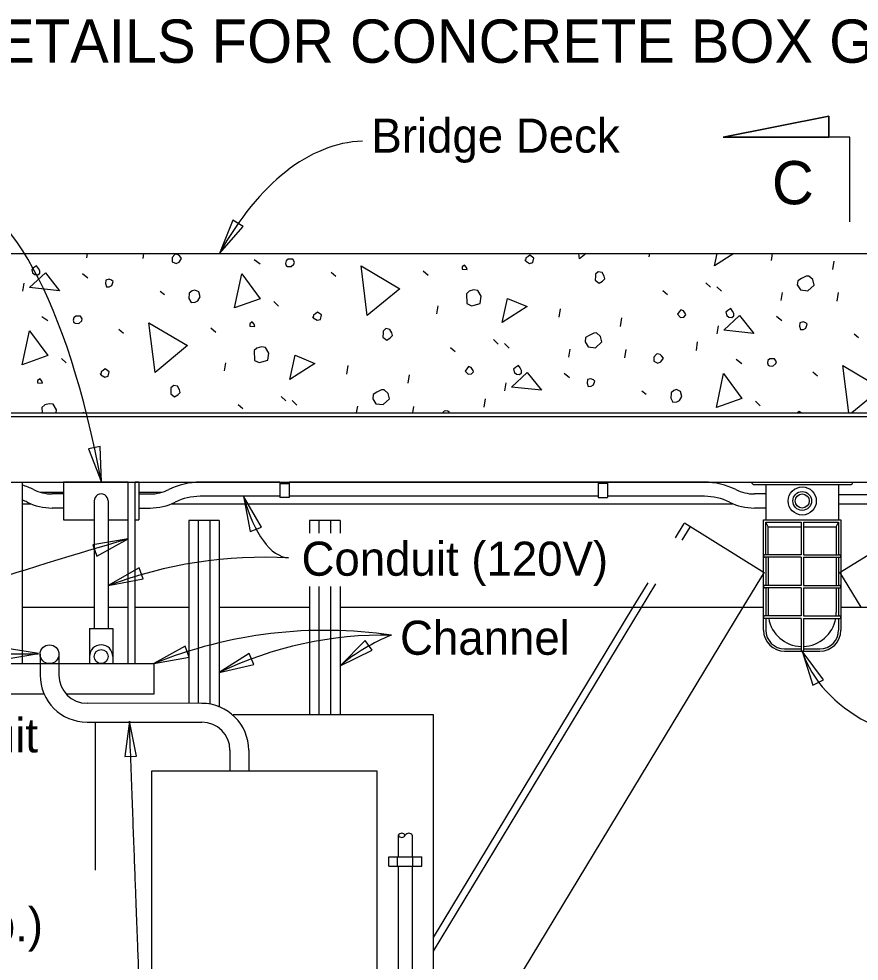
# Model space of a CAD drawing. Extents: x 0 to 30.8, y 0 to 21.2.
# Drawn here: x 4.493 to 8.221, y 5.394 to 9.576 of the extents above; entities that cross this region are included whole.
import ezdxf

# ---------------------------------------------------------------- set-up
doc = ezdxf.new("R2010")
doc.units = 0
for name, color, linetype in [('Dimension', 7, 'Continuous'), ('Lighting', 7, 'Continuous'), ('Miscellaneous', 7, 'Continuous'), ('SteelGirder', 7, 'Continuous'), ('SteelGirder_h', 7, 'Continuous'), ('SupstrConc', 7, 'Continuous'), ('TextStructures', 7, 'Continuous')]:
    doc.layers.add(name, color=color, linetype=linetype)

msp = doc.modelspace()

# ---------------------------------------------------------------- linework, layer by layer
at = {"layer": 'Dimension'}
for p, q in [((7.6172, 9.0507), (8.0859, 9.1444)), ((8.0859, 9.1444), (8.0859, 9.0507)), ((8.1797, 9.0507), (7.6172, 9.0507)), ((8.1797, 8.6757), (8.1797, 9.0507))]:
    msp.add_line(p, q, dxfattribs=at)
for points in [[(8.0859, 9.0507), (8.0859, 9.1444), (7.6172, 9.0507)], [(5.3832, 8.5353), (5.4879, 8.6542), (5.4428, 8.682)], [(4.8595, 7.5197), (4.8546, 7.678), (4.8027, 7.6676)], [(5.4894, 7.4572), (5.5198, 7.3017), (5.5693, 7.3204)], [(4.9783, 7.2679), (4.822, 7.2423), (4.8391, 7.1922)], [(4.8897, 7.0606), (5.0452, 7.0907), (5.0266, 7.1402)], [(5.918, 6.705), (6.0607, 6.7738), (6.03, 6.8169)], [(4.5805, 6.7589), (4.4243, 6.7853), (4.4243, 6.7324)], [(5.0928, 6.7147), (5.2487, 6.7428), (5.2307, 6.7925)], [(5.3822, 6.6746), (5.5364, 6.7111), (5.5157, 6.7599)], [(7.9682, 6.7697), (8.0155, 6.6185), (8.0627, 6.6425)], [(4.9837, 6.4589), (4.963, 6.3018), (5.0159, 6.3037)]]:
    msp.add_lwpolyline(points, close=True, dxfattribs=at)
for centre, radius, start, end in [((5.5854, 5.207), 1.9799, 86.9707, 110.5746), ((5.8523, 4.8354), 2.0269, 81.6635, 112.0069), ((6.1133, 5.1541), 1.6871, 88.8828, 115.6789), ((6.4507, 6.0706), 0.8283, 111.5678, 130.0212)]:
    msp.add_arc(centre, radius, start, end, dxfattribs=at)
for centre, major_axis, ratio, start_param, end_param in [((6.1283, 6.6665), (0.1111, -2.3674), 0.464296, 3.141604, 3.781059), ((4.1852, 6.2941), (0.0332, -2.5173), 0.313255, 2.075166, 3.141607), ((5.7691, 8.2544), (0.079, 1.0703), 0.315754, 2.434073, 3.141613), ((9.2695, 7.2066), (1.3013, 0.4369), 0.58496, 3.141593, 4.152777)]:
    msp.add_ellipse(centre, major_axis=major_axis, ratio=ratio, start_param=start_param, end_param=end_param, dxfattribs=at)
for points, degree in [([(4.9783, 7.2679), (4.6826, 7.1814), (4.1926, 7.0333), (3.6822, 6.8035), (3.5444, 6.6555), (3.3556, 6.3798), (3.4596, 6.0576), (3.4353, 5.8356), (3.5477, 5.8254)], 3), ([(3.8226, 6.4065), (3.7639, 6.427), (3.7332, 6.478), (3.8583, 6.6108), (4.1824, 6.7333), (4.3074, 6.7588), (4.5805, 6.7588)], 2), ([(2.6234, 4.9322), (4.0961, 4.9424), (5.0399, 4.9935), (5.0194, 5.4888), (4.9837, 6.4589)], 2)]:
    msp.add_open_spline(points, degree=degree, dxfattribs=at)
at = {"layer": 'Lighting'}
for p, q in [((4.6917, 7.5197), (4.6917, 7.353)), ((4.9783, 7.5197), (4.6917, 7.5197)), ((5.025, 7.5197), (5.0095, 7.5197)), ((5.025, 7.5197), (5.025, 7.353)), ((5.6513, 7.5197), (5.297, 7.5197)), ((7.0625, 7.5197), (5.693, 7.5197)), ((7.5342, 7.5197), (7.1042, 7.5197)), ((7.7443, 7.5197), (8.1922, 7.5197)), ((7.7547, 7.5093), (8.1818, 7.5093)), ((7.8068, 7.5197), (8.1297, 7.5197)), ((7.8068, 7.5093), (7.8068, 7.353)), ((8.1297, 7.5093), (8.1297, 7.353)), ((4.6917, 7.4676), (4.6414, 7.4676)), ((5.025, 7.4676), (5.0754, 7.4676)), ((5.6513, 7.4572), (5.2969, 7.4572)), ((7.0625, 7.4572), (5.693, 7.4572)), ((7.5347, 7.4572), (7.1042, 7.4572)), ((7.8068, 7.4676), (7.7564, 7.4676)), ((4.6917, 7.4051), (4.6414, 7.4051)), ((4.8271, 7.4364), (4.8271, 6.8702)), ((4.8896, 7.4364), (4.8896, 6.8702)), ((5.025, 7.4051), (5.0754, 7.4051)), ((7.8068, 7.4051), (7.7564, 7.4051)), ((4.6917, 7.353), (4.8271, 7.353)), ((4.8896, 7.353), (4.9783, 7.353)), ((5.0095, 7.353), (5.025, 7.353)), ((5.2468, 7.3502), (5.2468, 6.5383)), ((5.3822, 7.3502), (5.2468, 7.3502)), ((5.2884, 7.3502), (5.2884, 6.5383)), ((5.3406, 7.3502), (5.3406, 6.5352)), ((5.3822, 7.3502), (5.3822, 6.5233)), ((5.918, 7.3502), (5.7826, 7.3502)), ((5.7826, 7.3502), (5.7826, 7.2938)), ((5.8242, 7.3502), (5.8242, 7.2938)), ((5.8764, 7.3502), (5.8764, 7.2938)), ((5.918, 7.3502), (5.918, 7.2938)), ((7.7964, 6.8634), (7.7964, 7.353)), ((7.7964, 7.353), (7.8068, 7.353)), ((7.8068, 7.353), (8.1297, 7.353)), ((7.8068, 7.1968), (7.8068, 7.3426)), ((7.8068, 7.3426), (7.963, 7.3426)), ((7.8172, 7.3218), (7.8068, 7.3426)), ((7.8172, 7.3218), (7.963, 7.3218)), ((7.963, 7.3426), (7.963, 7.1968)), ((7.9734, 7.3426), (8.1297, 7.3426)), ((7.9734, 7.3426), (7.9734, 7.1968)), ((7.9734, 7.3218), (8.1193, 7.3218)), ((8.1193, 7.3218), (8.1297, 7.3426)), ((8.1297, 7.353), (8.1401, 7.353)), ((8.1297, 7.3426), (8.1297, 7.1968)), ((8.1401, 7.353), (8.1401, 6.8634)), ((7.963, 7.1968), (7.8016, 7.1968)), ((7.9734, 7.1968), (8.1349, 7.1968)), ((7.963, 7.1864), (7.8016, 7.1864)), ((7.8068, 7.1864), (7.8068, 7.0614)), ((7.963, 7.1864), (7.963, 7.0614)), ((7.9734, 7.1864), (8.1349, 7.1864)), ((7.9734, 7.1864), (7.9734, 7.0614)), ((8.1297, 7.1864), (8.1297, 7.0614)), ((5.7826, 7.057), (5.7826, 6.4871)), ((5.8242, 7.057), (5.8242, 6.4871)), ((5.8764, 7.057), (5.8764, 6.4871)), ((5.918, 7.057), (5.918, 6.4871)), ((7.963, 7.0614), (7.8016, 7.0614)), ((7.963, 7.051), (7.8016, 7.051)), ((7.8068, 7.051), (7.8068, 6.926)), ((7.963, 7.051), (7.963, 6.926)), ((7.9734, 7.0614), (8.1349, 7.0614)), ((7.9734, 7.051), (8.1349, 7.051)), ((7.9734, 7.051), (7.9734, 6.926)), ((8.1297, 7.051), (8.1297, 6.926)), ((7.963, 6.926), (7.8016, 6.926)), ((7.963, 6.9156), (7.8016, 6.9156)), ((7.8068, 6.9156), (7.8068, 6.8634)), ((7.963, 6.9156), (7.963, 6.7749)), ((7.9734, 6.926), (8.1349, 6.926)), ((7.9734, 6.9156), (8.1349, 6.9156)), ((7.9734, 6.9156), (7.9734, 6.7749)), ((8.1297, 6.9156), (8.1297, 6.8634)), ((4.8063, 6.8702), (4.9104, 6.8702)), ((4.8063, 6.8702), (4.8063, 6.7147)), ((4.9104, 6.8702), (4.9104, 6.7147)), ((7.8901, 6.7801), (7.963, 6.7801)), ((7.9734, 6.7801), (8.0464, 6.7801)), ((4.5876, 6.7563), (4.5876, 6.6634)), ((4.6709, 6.7563), (4.6709, 6.6635)), ((7.8901, 6.7697), (8.0464, 6.7697)), ((4.3949, 6.7147), (5.0928, 6.7147)), ((5.0928, 6.7147), (5.0928, 6.5793)), ((4.6053, 6.5793), (4.3949, 6.5793)), ((5.0928, 6.5793), (4.7035, 6.5793)), ((5.3047, 6.5383), (4.7959, 6.5385)), ((4.7958, 6.4551), (5.3046, 6.4549)), ((5.4296, 6.3299), (5.4296, 6.2371)), ((5.513, 6.33), (5.513, 6.2371)), ((6.1761, 5.9527), (6.1761, 5.8576)), ((6.2387, 5.9527), (6.2387, 5.8576)), ((6.1761, 5.8159), (6.1761, 3.9083)), ((6.2387, 5.8159), (6.2387, 3.9083))]:
    msp.add_line(p, q, dxfattribs=at)
msp.add_lwpolyline([(6.0824, 6.2371), (5.0824, 6.2371), (5.0824, 3.4871), (6.0824, 3.4871)], close=True, dxfattribs=at)
for centre, radius in [((7.9682, 7.4364), 0.0625), ((7.9682, 7.4364), 0.0417), ((7.9682, 7.4364), 0.0312), ((4.6293, 6.7563), 0.0416), ((4.8584, 6.7459), 0.0312)]:
    msp.add_circle(centre, radius, dxfattribs=at)
for centre, radius, start, end in [((4.4191, 7.2072), 0.3125, 63.6116, 73.2157), ((4.6414, 7.6551), 0.1875, 243.6116, 270.0001), ((5.0754, 7.6551), 0.1875, 270.0001, 296.3886), ((5.2976, 7.2072), 0.3125, 90.0002, 116.3886), ((7.5342, 7.2072), 0.3125, 63.6115, 90.0001), ((7.7564, 7.6551), 0.1875, 243.6115, 270), ((7.7547, 7.5197), 0.0104, 180, 270), ((8.1818, 7.5197), 0.0104, 270, 0), ((4.8584, 7.4364), 0.0312, 359.9876, 180.0001), ((5.2976, 7.2072), 0.25, 90.0002, 116.3886), ((7.5342, 7.2072), 0.25, 63.6115, 89.8816), ((4.4191, 7.2072), 0.25, 63.6116, 68.8407), ((4.6414, 7.6551), 0.25, 243.6116, 270.0001), ((5.0754, 7.6551), 0.25, 270.0001, 296.3886), ((7.7564, 7.6551), 0.25, 243.6115, 270), ((7.8016, 7.1916), 0.0052, 89.9999, 270), ((8.1349, 7.1916), 0.0052, 270, 90.0001), ((7.8016, 7.0562), 0.0052, 89.9999, 270), ((8.1349, 7.0562), 0.0052, 270, 90.0001), ((7.8016, 6.9208), 0.0052, 89.9999, 270), ((8.1349, 6.9208), 0.0052, 270, 90.0001), ((7.8901, 6.8634), 0.0937, 180, 270), ((7.8901, 6.8634), 0.0833, 180, 270), ((8.0464, 6.8634), 0.0833, 270, 360), ((8.0464, 6.8634), 0.0937, 270, 360), ((4.8584, 6.7459), 0.052, 0.0163, 179.7051), ((7.9682, 6.7749), 0.0052, 179.9665, 0), ((4.7959, 6.6634), 0.2083, 180, 269.9792), ((4.7959, 6.6635), 0.125, 180, 269.9792), ((5.3047, 6.33), 0.2083, 0, 89.9792), ((5.3046, 6.3299), 0.125, 0, 89.9792), ((6.1918, 5.944), 0.0179, 29.0027, 150.9974), ((6.1918, 5.9614), 0.0179, 209.003, 330.9971), ((6.2231, 5.944), 0.0179, 29.0028, 150.9973)]:
    msp.add_arc(centre, radius, start, end, dxfattribs=at)
at = {"layer": 'Miscellaneous'}
for p, q in [((4.7952, 8.5161), (4.7985, 8.5353)), ((5.0445, 8.513), (5.0477, 8.5353)), ((7.2894, 8.5192), (7.2922, 8.5353)), ((7.8318, 8.5041), (7.8363, 8.5353)), ((5.5376, 8.508), (5.5634, 8.489)), ((8.1042, 8.4632), (8.1096, 8.5009)), ((5.8788, 8.4519), (5.8991, 8.434)), ((6.2862, 8.4575), (6.3096, 8.4379)), ((4.7752, 8.446), (4.7986, 8.4264)), ((4.5115, 8.3676), (4.5176, 8.4029)), ((5.1197, 8.3675), (5.1394, 8.3521)), ((7.3501, 8.3699), (7.3704, 8.352)), ((7.54, 8.4052), (7.5609, 8.3849)), ((7.5888, 8.3872), (7.6097, 8.367)), ((7.8742, 8.3265), (7.8803, 8.3618)), ((8.1235, 8.3235), (8.1289, 8.3611)), ((5.6239, 8.3214), (5.6448, 8.3012)), ((6.3476, 8.2669), (6.3537, 8.3022)), ((6.89, 8.2518), (6.8955, 8.2895)), ((4.5959, 8.2556), (4.6216, 8.2367)), ((7.1624, 8.2109), (7.1678, 8.2486)), ((7.8542, 8.2565), (7.8775, 8.2368)), ((4.937, 8.1995), (4.9573, 8.1817)), ((5.3444, 8.2051), (5.3678, 8.1855)), ((7.5905, 8.178), (7.5966, 8.2133)), ((8.1987, 8.178), (8.2184, 8.1625)), ((6.4084, 8.1175), (6.4287, 8.0997)), ((6.5982, 8.1529), (6.6191, 8.1326)), ((6.647, 8.1349), (6.668, 8.1146)), ((7.4989, 8.1043), (7.5044, 8.142)), ((6.9324, 8.0742), (6.9385, 8.1095)), ((7.1817, 8.0711), (7.1872, 8.1088)), ((4.6821, 8.0691), (4.703, 8.0488)), ((5.4058, 8.0145), (5.4119, 8.0498)), ((5.9482, 7.9994), (5.9537, 8.0371)), ((7.6748, 8.0661), (7.7006, 8.0471)), ((6.2206, 7.9585), (6.226, 7.9962)), ((6.9124, 8.0041), (6.9358, 7.9845)), ((8.016, 8.0099), (8.0363, 7.9921)), ((6.6487, 7.9257), (6.6548, 7.961)), ((7.2569, 7.9256), (7.2766, 7.9102)), ((5.4666, 7.8652), (5.4869, 7.8473)), ((5.6564, 7.9005), (5.6774, 7.8802)), ((5.7052, 7.8825), (5.7262, 7.8623)), ((6.5572, 7.852), (6.5626, 7.8897)), ((7.761, 7.8795), (7.782, 7.8593)), ((3.9317, 7.827), (8.7519, 7.827)), ((5.9915, 7.827), (5.9967, 7.8571)), ((6.2411, 7.827), (6.2454, 7.8564)), ((3.9359, 7.8114), (8.7519, 7.8114)), ((3.2598, 7.5197), (8.7519, 7.5197)), ((7.8172, 7.1968), (7.8172, 7.3218)), ((8.1193, 7.3218), (8.1193, 7.1968)), ((7.8172, 7.1864), (7.8172, 7.0614)), ((8.1193, 7.1864), (8.1193, 7.0614)), ((7.8172, 7.051), (7.8172, 6.9415)), ((8.1193, 7.051), (8.1193, 6.9415))]:
    msp.add_line(p, q, dxfattribs=at)
for points in [[(5.173, 8.5164), (5.1727, 8.4982), (5.1905, 8.49), (5.2043, 8.4963), (5.2155, 8.5123), (5.2075, 8.523), (5.2007, 8.529), (5.1898, 8.5312), (5.1849, 8.5299), (5.173, 8.5164)], [(6.9809, 8.5116), (6.9779, 8.5353)], [(7.0096, 8.5353), (6.9809, 8.5116)], [(7.5793, 8.4805), (7.5911, 8.5353)], [(7.6646, 8.5353), (7.5793, 8.4805)], [(5.6794, 8.4812), (5.6855, 8.4777), (5.7013, 8.4768), (5.7138, 8.4879), (5.7167, 8.4964), (5.708, 8.5096), (5.6874, 8.5093), (5.679, 8.5019), (5.6768, 8.4909), (5.6794, 8.4812)], [(6.7403, 8.5015), (6.7587, 8.4909), (6.7731, 8.4948), (6.7783, 8.5143), (6.7593, 8.5273), (6.7509, 8.5199), (6.7419, 8.5149), (6.7403, 8.5015), (6.739, 8.5063)], [(4.5409, 8.3833), (4.6114, 8.4487), (4.674, 8.3697), (4.5409, 8.3833)], [(4.5544, 8.449), (4.5642, 8.4413), (4.5776, 8.4397), (4.586, 8.4471), (4.5858, 8.4574), (4.5801, 8.4688), (4.5721, 8.4796), (4.5589, 8.4709), (4.5505, 8.4635), (4.5544, 8.449)], [(6.0391, 8.2593), (6.0111, 8.4796), (6.1832, 8.3781), (6.0391, 8.2593)], [(6.4601, 8.4653), (6.4814, 8.4632), (6.4788, 8.4729), (6.4707, 8.4836), (6.4599, 8.4756), (6.4601, 8.4653)], [(7.0507, 8.4346), (7.0504, 8.4164), (7.067, 8.4027), (7.0826, 8.4121), (7.0927, 8.4225), (7.0895, 8.4346), (7.0801, 8.4502), (7.0637, 8.4536), (7.0512, 8.4425), (7.0507, 8.4346)], [(4.8778, 8.4011), (4.8817, 8.3866), (4.8944, 8.3874), (4.9059, 8.393), (4.9116, 8.4101), (4.9049, 8.4161), (4.8933, 8.4207), (4.8788, 8.4168), (4.8778, 8.4011)], [(5.4503, 8.293), (5.4823, 8.444), (5.5636, 8.3338), (5.4503, 8.293)], [(7.9464, 8.3951), (7.9601, 8.3729), (7.9924, 8.3685), (8.0216, 8.3945), (8.0152, 8.4187), (7.9979, 8.4347), (7.9852, 8.4339), (7.9648, 8.4233), (7.9491, 8.4139), (7.9464, 8.3951)], [(5.2491, 8.3582), (5.2476, 8.3345), (5.2577, 8.3165), (5.2752, 8.3186), (5.2866, 8.3242), (5.2972, 8.3426), (5.2914, 8.3644), (5.2737, 8.3725), (5.2616, 8.3693), (5.2491, 8.3582)], [(6.4789, 8.3564), (6.4803, 8.3128), (6.5011, 8.3028), (6.5131, 8.3061), (6.5397, 8.3132), (6.544, 8.3454), (6.5296, 8.37), (6.5108, 8.3727), (6.4915, 8.3676), (6.4789, 8.3564)], [(6.6375, 8.2281), (6.6606, 8.3352), (6.7479, 8.2991), (6.6375, 8.2281)], [(7.4144, 8.2654), (7.4285, 8.2511), (7.4437, 8.2526), (7.4514, 8.2624), (7.4501, 8.2673), (7.4414, 8.2804), (7.4298, 8.2851), (7.4221, 8.2753), (7.4144, 8.2654)], [(7.6334, 8.2594), (7.6432, 8.2517), (7.6566, 8.2501), (7.6649, 8.2575), (7.6648, 8.2678), (7.6591, 8.2793), (7.6511, 8.29), (7.6379, 8.2813), (7.6295, 8.2739), (7.6334, 8.2594)], [(4.7376, 8.2289), (4.7437, 8.2254), (4.7595, 8.2244), (4.7721, 8.2355), (4.7749, 8.2441), (4.7662, 8.2573), (4.7456, 8.2569), (4.7373, 8.2495), (4.735, 8.2386), (4.7376, 8.2289)], [(5.7985, 8.2492), (5.8169, 8.2386), (5.8314, 8.2424), (5.8365, 8.2619), (5.8175, 8.275), (5.8091, 8.2675), (5.8001, 8.2625), (5.7985, 8.2492), (5.7972, 8.254)], [(7.6199, 8.1937), (7.6904, 8.2592), (7.753, 8.1802), (7.6199, 8.1937)], [(5.0973, 8.0069), (5.0693, 8.2272), (5.2415, 8.1258), (5.0973, 8.0069)], [(5.5183, 8.2129), (5.5396, 8.2109), (5.537, 8.2205), (5.5289, 8.2313), (5.5182, 8.2232), (5.5183, 8.2129)], [(6.1089, 8.1822), (6.1086, 8.164), (6.1252, 8.1504), (6.1408, 8.1597), (6.151, 8.1702), (6.1477, 8.1823), (6.1384, 8.1979), (6.1219, 8.2012), (6.1094, 8.1901), (6.1089, 8.1822)], [(7.9568, 8.2115), (7.9607, 8.197), (7.9734, 8.1978), (7.9848, 8.2035), (7.9906, 8.2206), (7.9838, 8.2265), (7.9722, 8.2312), (7.9577, 8.2273), (7.9568, 8.2115)], [(4.5085, 8.0407), (4.5405, 8.1916), (4.6218, 8.0814), (4.5085, 8.0407)], [(7.0047, 8.1427), (7.0184, 8.1205), (7.0506, 8.1162), (7.0799, 8.1422), (7.0734, 8.1663), (7.0561, 8.1824), (7.0434, 8.1816), (7.023, 8.1709), (7.0074, 8.1616), (7.0047, 8.1427)], [(5.5372, 8.1041), (5.5385, 8.0604), (5.5593, 8.0505), (5.5714, 8.0537), (5.5979, 8.0608), (5.6022, 8.093), (5.5879, 8.1177), (5.569, 8.1204), (5.5497, 8.1152), (5.5372, 8.1041)], [(5.6958, 7.9758), (5.7188, 8.0829), (5.8062, 8.0468), (5.6958, 7.9758)], [(7.3102, 8.0745), (7.3099, 8.0563), (7.3277, 8.0481), (7.3415, 8.0544), (7.3527, 8.0703), (7.3447, 8.0811), (7.3379, 8.0871), (7.327, 8.0893), (7.3221, 8.088), (7.3102, 8.0745)], [(6.4726, 8.0131), (6.4868, 7.9988), (6.5019, 8.0002), (6.5096, 8.0101), (6.5083, 8.0149), (6.4996, 8.0281), (6.488, 8.0328), (6.4803, 8.0229), (6.4726, 8.0131)], [(6.6916, 8.0071), (6.7014, 7.9994), (6.7148, 7.9978), (6.7232, 8.0052), (6.723, 8.0155), (6.7173, 8.0269), (6.7093, 8.0377), (6.6961, 8.029), (6.6877, 8.0216), (6.6916, 8.0071)], [(7.8166, 8.0393), (7.8227, 8.0358), (7.8385, 8.0349), (7.851, 8.046), (7.8539, 8.0545), (7.8452, 8.0677), (7.8246, 8.0674), (7.8162, 8.0599), (7.814, 8.049), (7.8166, 8.0393)], [(8.1751, 7.827), (8.1483, 8.0376), (8.3204, 7.9362), (8.188, 7.827)], [(4.8567, 7.9968), (4.8751, 7.9862), (4.8896, 7.9901), (4.8947, 8.0096), (4.8757, 8.0226), (4.8673, 8.0152), (4.8583, 8.0102), (4.8567, 7.9968), (4.8554, 8.0017)], [(6.6781, 7.9414), (6.7486, 8.0068), (6.8112, 7.9278), (6.6781, 7.9414)], [(7.5875, 7.8511), (7.6195, 8.0021), (7.7008, 7.8918), (7.5875, 7.8511)], [(4.5766, 7.9606), (4.5978, 7.9585), (4.5952, 7.9682), (4.5872, 7.9789), (4.5764, 7.9709), (4.5766, 7.9606)], [(5.1671, 7.9299), (5.1668, 7.9117), (5.1834, 7.898), (5.199, 7.9074), (5.2092, 7.9179), (5.2059, 7.9299), (5.1966, 7.9455), (5.1802, 7.9489), (5.1676, 7.9378), (5.1671, 7.9299)], [(7.015, 7.9591), (7.0189, 7.9447), (7.0316, 7.9455), (7.0431, 7.9511), (7.0488, 7.9682), (7.0421, 7.9742), (7.0305, 7.9788), (7.016, 7.9749), (7.015, 7.9591)], [(6.0629, 7.8904), (6.0766, 7.8682), (6.1088, 7.8639), (6.1381, 7.8898), (6.1316, 7.914), (6.1144, 7.93), (6.1016, 7.9292), (6.0812, 7.9186), (6.0656, 7.9092), (6.0629, 7.8904)], [(7.3863, 7.9163), (7.3848, 7.8926), (7.3949, 7.8746), (7.4124, 7.8767), (7.4238, 7.8823), (7.4344, 7.9007), (7.4286, 7.9224), (7.4109, 7.9306), (7.3988, 7.9274), (7.3863, 7.9163)], [(4.6586, 7.827), (4.6604, 7.8407), (4.6461, 7.8653), (4.6272, 7.868), (4.6079, 7.8629), (4.5954, 7.8517)], [(4.5954, 7.8517), (4.5961, 7.827)], [(4.7763, 7.827), (4.7771, 7.8305), (4.7855, 7.827)], [(6.4042, 7.827), (6.4029, 7.8288), (6.3961, 7.8347), (6.3852, 7.837), (6.3804, 7.8357), (6.3728, 7.827)], [(7.9635, 7.827), (7.9547, 7.833), (7.9479, 7.827)]]:
    msp.add_lwpolyline(points, dxfattribs=at)
for start, end in [(180, 185.9203), (189.9053, 268.0265), (271.9735, 350.0947), (354.0797, 0)]:
    msp.add_arc((7.9682, 6.9415), 0.151, start, end, dxfattribs=at)
at = {"layer": 'SteelGirder'}
for p, q in [((4.5094, 6.7147), (4.5094, 7.5197)), ((4.9783, 6.7147), (4.9783, 7.5197)), ((5.0095, 6.7147), (5.0095, 7.5197)), ((5.6513, 7.5197), (5.6513, 7.452)), ((5.6513, 7.5197), (5.693, 7.5197)), ((5.6513, 7.5145), (5.693, 7.5145)), ((5.693, 7.5197), (5.693, 7.452)), ((7.0625, 7.5197), (7.0625, 7.452)), ((7.1042, 7.5197), (7.0625, 7.5197)), ((7.1042, 7.5145), (7.0625, 7.5145)), ((7.1042, 7.5197), (7.1042, 7.452)), ((4.5893, 7.475), (4.6917, 7.475)), ((5.025, 7.475), (5.1273, 7.475)), ((5.693, 7.452), (5.6513, 7.452)), ((7.0625, 7.452), (7.1042, 7.452)), ((8.1297, 7.4647), (8.7519, 7.4647)), ((4.5094, 7.4231), (4.5483, 7.4231)), ((5.1684, 7.4231), (7.6634, 7.4231)), ((8.1297, 7.4231), (8.7519, 7.4231)), ((4.5094, 6.9647), (4.8271, 6.9647)), ((4.8896, 6.9647), (4.9783, 6.9647)), ((5.0095, 6.9647), (5.2468, 6.9647)), ((5.3822, 6.9647), (5.7826, 6.9647)), ((5.918, 6.9647), (7.7963, 6.9647)), ((6.3324, 5.4991), (7.219, 6.9647)), ((6.3324, 4.6939), (7.7061, 6.9647)), ((8.14, 6.9647), (8.7519, 6.9647)), ((6.1341, 5.8576), (6.2807, 5.8576)), ((6.1341, 5.8159), (6.1341, 5.8576)), ((6.1735, 5.8159), (6.1735, 5.8576)), ((6.2413, 5.8159), (6.2413, 5.8576)), ((6.2807, 5.8159), (6.2807, 5.8576)), ((6.1341, 5.8159), (6.2807, 5.8159))]:
    msp.add_line(p, q, dxfattribs=at)
for points in [[(6.2101, 3.2371), (6.3324, 3.2371), (6.3324, 6.4871), (5.4444, 6.4871)], [(4.8324, 6.4551), (4.8324, 5.7977)]]:
    msp.add_lwpolyline(points, dxfattribs=at)
at = {"layer": 'SteelGirder_h'}
for p, q in [((7.4057, 7.2734), (7.4441, 7.3368)), ((7.4359, 7.263), (7.4708, 7.3207)), ((7.4454, 7.339), (7.7993, 7.1189)), ((8.4908, 7.339), (8.1369, 7.1189)), ((7.7061, 6.9647), (7.8007, 7.1211)), ((8.2302, 6.9647), (8.1356, 7.1211)), ((6.3324, 5.4388), (7.3183, 7.0686)), ((7.219, 6.9647), (7.2846, 7.0732))]:
    msp.add_line(p, q, dxfattribs=at)
at = {"layer": 'SupstrConc'}
msp.add_line((0.2637, 8.5353), (8.7519, 8.5353), dxfattribs=at)

# ---------------------------------------------------------------- texts
at = {"layer": 'Dimension'}
for s, p in [('Conduit', (3.8811, 6.3208)), ('Rods (Typ.)', (3.5444, 5.4816))]:
    msp.add_text(s, height=0.1512, dxfattribs=at).set_placement(p)
at = {"layer": 'TextStructures'}
for s, height, p in [('LIGHTING DETAILS FOR CONCRETE BOX GIRDER BRIDGE', 0.192, (2.9236, 9.3811)), ('Bridge Deck', 0.1512, (6.0572, 8.9822)), ('C', 0.192, (7.834, 8.753)), ('Conduit (120V)', 0.1512, (5.7472, 7.1047)), ('Channel', 0.1512, (6.1844, 6.7539))]:
    msp.add_text(s, height=height, dxfattribs=at).set_placement(p)

doc.saveas('drawing.dxf')
